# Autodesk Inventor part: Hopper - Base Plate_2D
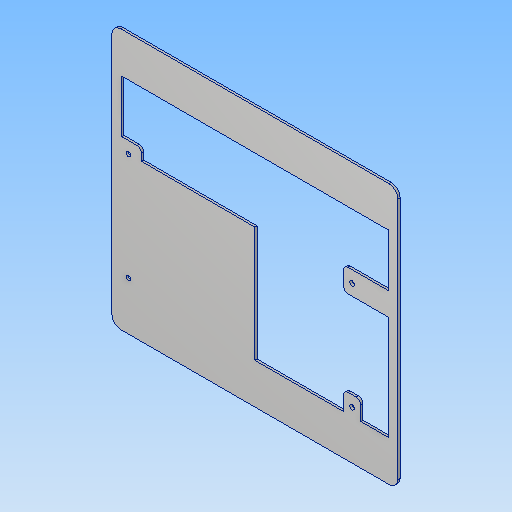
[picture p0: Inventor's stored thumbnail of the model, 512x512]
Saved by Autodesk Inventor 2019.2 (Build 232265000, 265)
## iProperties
Created: 2019-02
Part Number: Hopper - Base Plate_2D
Material: Aluminum 6061
Document SubType Name: Modeling
Designer: User
Density: 2.7 g/cm^3
Appearance: Aluminum - Flat
Author: User
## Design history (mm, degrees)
sketch "per - Base Plate sketch"
  geometry: L1 (164.534, -61.012)-(164.534, -51.013); L2 (167.709, -47.838)-(196.195, -47.838); L3 (196.195, -47.838)-(196.195, -10.596); L4 (196.195, -10.596)-(7.005, -10.596); L5 (7.005, -10.596)-(7.005, -47.838); L6 (7.005, -47.838)-(17.843, -47.838); L7 (21.018, -51.013)-(21.018, -56.013); L8 (21.018, -56.013)-(101.6, -56.216); L9 (101.6, -56.216)-(101.6, -138.11); L10 (101.6, -138.11)-(164.534, -138.11); L11 (164.534, -138.11)-(164.534, -127.918); L12 (167.709, -124.743)-(173.579, -124.743); L13 (176.754, -127.918)-(176.754, -138.11); L14 (176.754, -138.11)-(196.195, -138.11); L15 (196.195, -138.11)-(196.195, -64.187); L16 (196.195, -64.187)-(167.709, -64.187); L17 (6.35, 18.121)-(196.85, 18.121); L18 (203.2, 11.771)-(203.2, -160.478); L19 (196.85, -166.828)-(6.35, -166.828); L20 (0, -160.478)-(0, 11.771); C1 r 1.651 at (11.713, -132.416); C2 r 1.651 at (11.713, -56.216); C3 r 1.651 at (170.599, -56.216); C4 r 1.651 at (170.599, -132.416); A1 r 3.175 centre (167.709, -51.013) between (167.709, -47.838) and (164.534, -51.013); A2 r 3.175 centre (17.843, -51.013) between (21.018, -51.013) and (17.843, -47.838); A3 r 3.175 centre (167.709, -127.918) between (167.709, -124.743) and (164.534, -127.918); A4 r 3.175 centre (173.579, -127.918) between (176.754, -127.918) and (173.579, -124.743); A5 r 3.175 centre (167.709, -61.012) between (164.534, -61.012) and (167.709, -64.187); A6 r 6.35 centre (6.35, 11.771) between (6.35, 18.121) and (0, 11.771); A7 r 6.35 centre (196.85, 11.771) between (203.2, 11.771) and (196.85, 18.121); A8 r 6.35 centre (196.85, -160.478) between (196.85, -166.828) and (203.2, -160.478); A9 r 6.35 centre (6.35, -160.478) between (0, -160.478) and (6.35, -166.828)
  constraints: 40 end point, 18 point on circle, 13 centre point
extrude "per - Base Plate extrude" new body sketch "per - Base Plate sketch" stored distance "d0" = 1.5875; taper "d1" = 0 deg
node "per - Base Plate"
